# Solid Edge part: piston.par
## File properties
Author: Robert a Rhodes jr
Template: normal.par
Last saved by: CADCIM
Revision: 13
Application: Solid Edge
Accuracy: 0.99
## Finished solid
Body 1: solid body, 42 faces, 58 edges, 16 vertices.
  Faces by surface: cylinder 21, plane 20, torus 1
  Edges by curve: circle 40, intersection 10, line 8
Bounding box of the edges (mm; curved faces can reach further): 93.000 x 93.000 x 66.000, from (-46.5, -46.5, -46) to (46.5, 46.5, 20).
Cylindrical faces by radius (mm): R10 x2, R15 x2, R19 x2, R37 x2, R38.5 x2, R42.5 x5, R46.5 x6
Toroidal faces (ring radius, tube radius in mm): R-5.5431 r189 x1
Planar faces by outward normal: +y 2, +z 7, -y 2, -z 9
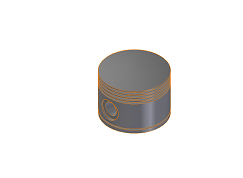
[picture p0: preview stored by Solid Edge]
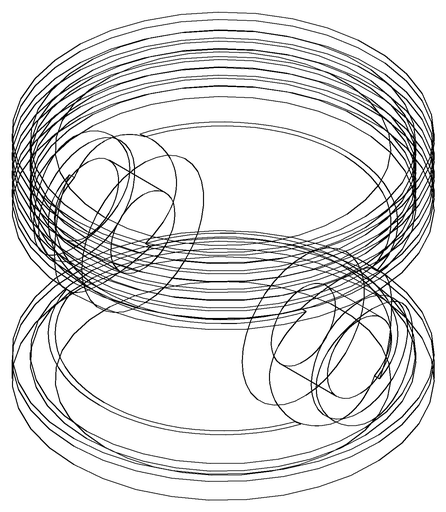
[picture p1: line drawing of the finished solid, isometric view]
